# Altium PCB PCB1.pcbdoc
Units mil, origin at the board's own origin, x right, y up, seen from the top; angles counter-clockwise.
Board outline 2533.91 x 1370 mil, 2 copper layers (Top Layer, Bottom Layer); 22 components, 28 nets, 122 pads, 66 vias.
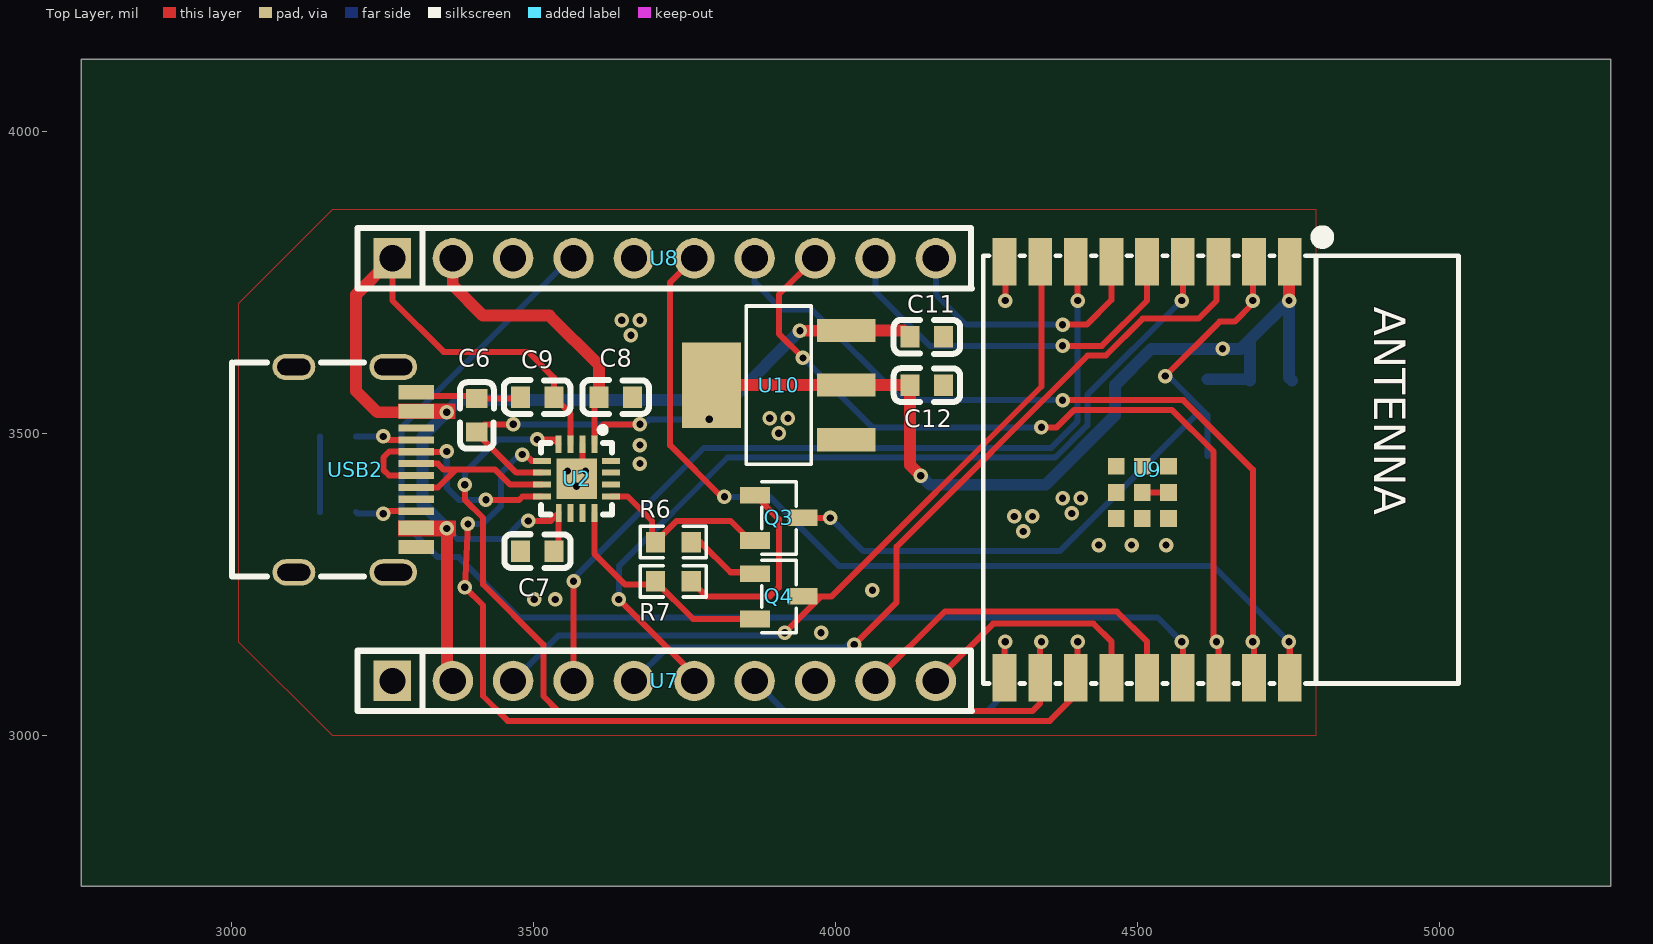
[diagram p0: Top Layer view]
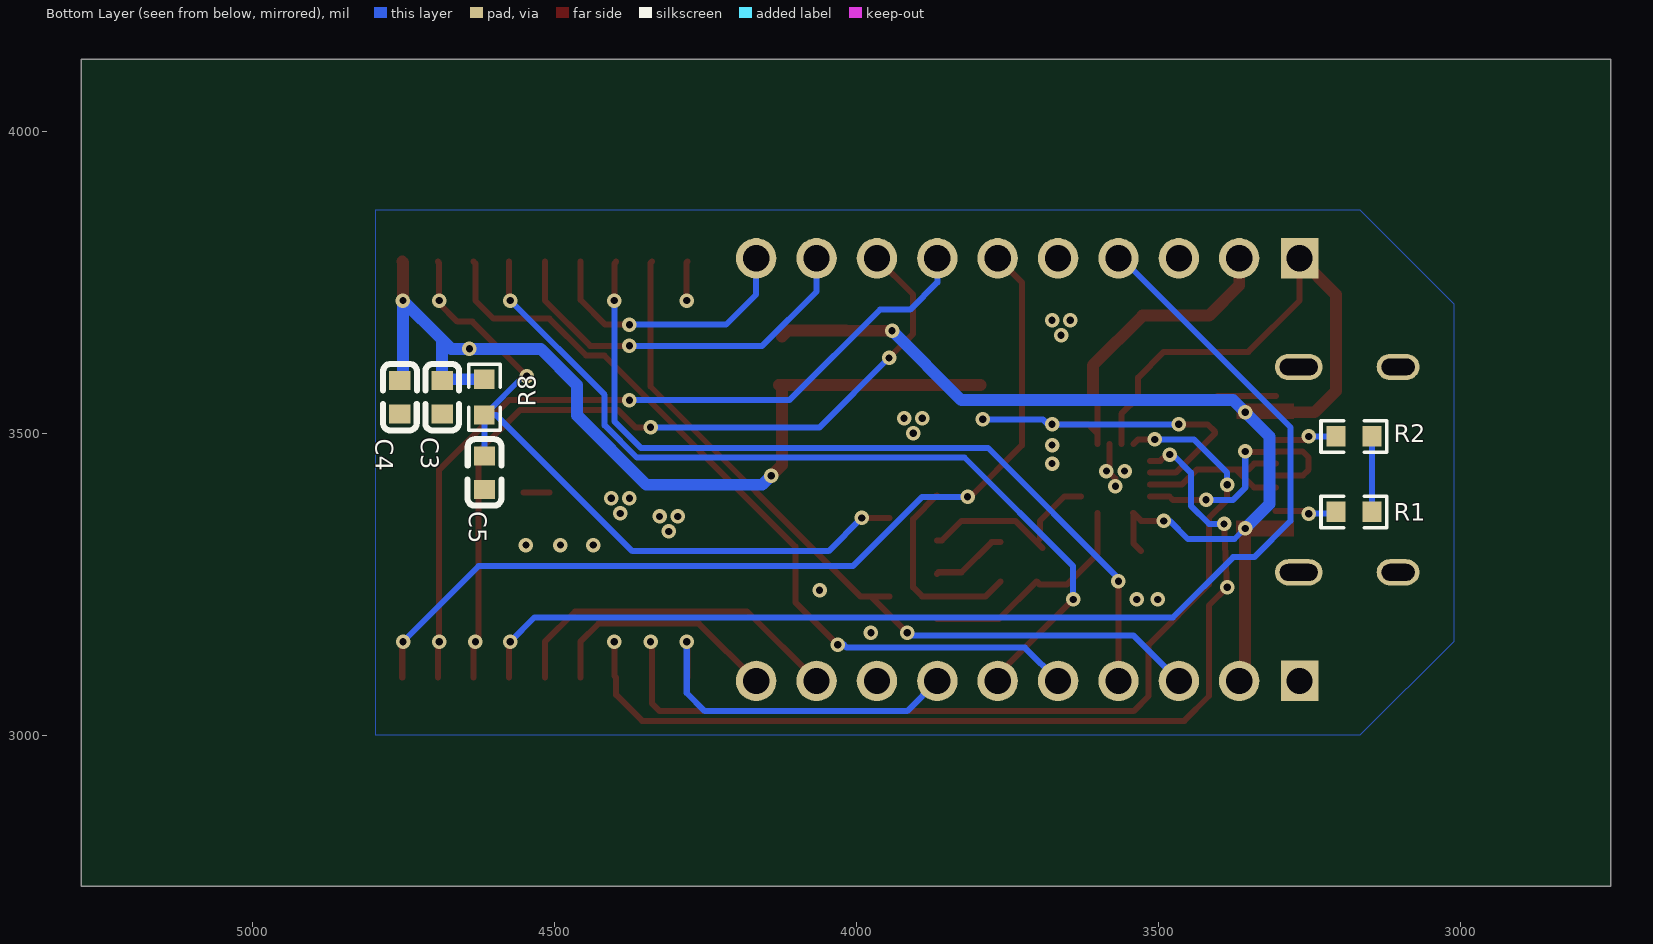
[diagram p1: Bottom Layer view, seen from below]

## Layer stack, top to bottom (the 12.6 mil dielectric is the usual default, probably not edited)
Top Solder: solder mask 0.4, Solder Resist, Dk 3.5
Top Layer: signal copper 1.4
Dielectric 1: dielectric 12.6, FR-4, Dk 4.8
Bottom Layer: signal copper 1.4
Bottom Solder: solder mask 0.4, Solder Resist, Dk 3.5

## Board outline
5283.91,2750 2750,2750 2750,4120 5283.91,4120

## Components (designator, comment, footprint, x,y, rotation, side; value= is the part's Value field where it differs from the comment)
C3 "0603F104Z500CT" C0603 4685.82,3559.7 r270 bottom
C4 "0603F104Z500CT" C0603 4755.82,3559.7 r270 bottom
C5 "0603F104Z500CT" C0603 4615.71,3435 r270 bottom
C6 "CC0603KRX7R8BB105" C0603 3405.71,3530 r90 top
C7 "CC0603KRX7R8BB105" C0603 3505.71,3305 r180 top
C8 "CC0603KRX7R8BB105" C0603 3635.71,3560 r0 top
C9 "0603F104Z500CT" C0603 3505.71,3560 r0 top
C11 "JMK107BC6106MA-T" C0603 4150.71,3660 r180 top
C12 "JMK107BC6106MA-T" C0603 4150.71,3580 r180 top
Q3 "S8050" SOT-23-3_L2.9-W1.3-P1.90-LS2.4-BR 3905.71,3360 r180 top
Q4 "S8050" SOT-23-3_L2.9-W1.3-P1.90-LS2.4-BR 3905.71,3230 r180 top
R1 "0603" R0603 3175.71,3370 r0 bottom
R2 "0603" R0603 3175.71,3495 r180 bottom
R6 "0603" R0603 3731.01,3320 r0 top
R7 "0603" R0603 3731.01,3255 r0 top
R8 "0603" R0603 4615.71,3560 r90 bottom
U2 "CH343P" TQFN-16_L3.0-W3.0-P0.50-BL-EP1.7 3570.71,3425 r180 top
U7 "cn10_2r54_10x1" HDR-TH_10P-P2.54-V-F 3715.71,3090 r0 top
U8 "cn10_2r54_10x1" HDR-TH_10P-P2.54-V-F 3715.71,3790 r0 top
U9 "ESP32-C3-WROOM-02D-N4" BULETM-SMD_18P-L20.0-W18.0-P1.50_ESP32-C3-WROOM 4515.71,3440 r270 top
U10 "AMS1117-1.5" SOT-223-4_L6.5-W3.5-P2.30-LS7.0-BR 3905.71,3580 r0 top
USB2 "TYPE-C母座16P" TYPE-C-SMD_16P-EH4 3203.9,3440 r270 top

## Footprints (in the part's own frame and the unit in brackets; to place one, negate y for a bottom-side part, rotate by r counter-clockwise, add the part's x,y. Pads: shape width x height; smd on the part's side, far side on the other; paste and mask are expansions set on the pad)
BULETM-SMD_18P-L20.0-W18.0-P1.50_ESP32-C3-WROOM [mil]
  rect 78.7x39.4 smd: 1(-344.5,236.2) 2(-344.5,177.2) 3(-344.5,118.1) 4(-344.5,59.1) 5(-344.5,0) 6(-344.5,-59) 7(-344.5,-118.1) 8(-344.5,-177.2) 9(-344.5,-236.2) 10(344.5,-236.2) 11(344.5,-177.2) 12(344.5,-118.1) 13(344.5,-59) 14(344.5,0) 15(344.5,59.1) 16(344.5,118.1) 17(344.5,177.2) 18(344.5,236.2)
  rect 27.6x27.6 smd: 19(-5.5,35.4) 19(-5.5,-7.9) 19(-5.5,-51.2) 19(37.8,35.4) 19(37.8,-7.9) 19(37.8,-51.2) 19(81.1,-7.9) 19(81.1,35.4) 19(81.1,-51.2)
  silkscreen extent -395,-272 354,516
C0603 [mm]
  rect 0.8x0.9 smd: 1(-0.7,0) 2(0.7,0)
  silkscreen extent -1.41,-0.71 1.39,0.72
HDR-TH_10P-P2.54-V-F [mil]
  rect 62x66.9 hole 43.3: 1(-450,0)
  round 66.9 hole 43.3: 2(-350,0) 3(-250,0) 4(-150,0) 5(-50,0) 6(50,0) 7(150,0) 8(250,0) 9(350,0) 10(450,0)
  silkscreen extent -508,-50 510,50
R0603 [mil]
  rect 31.75x34.02 smd: 1(-29.66,0) 2(29.66,0)
  silkscreen extent -55,-26 55,26
SOT-23-3_L2.9-W1.3-P1.90-LS2.4-BR [mm]
  rect 1.25x0.7 smd: 1(1,-0.95) 2(1,0.95) 3(-1,0)
  silkscreen extent -0.73,-1.53 0.73,1.53
SOT-223-4_L6.5-W3.5-P2.30-LS7.0-BR [mm]
  rect 2.47x0.98 smd: 1(2.835,-2.3) 2(2.835,0) 3(2.835,2.3)
  rect 2.47x3.6 smd: 4(-2.835,0)
  silkscreen extent -1.37,-3.33 1.37,3.33
TQFN-16_L3.0-W3.0-P0.50-BL-EP1.7 [mm]
  rect 0.25x0.75 smd: 1(-0.748,-1.45) 2(-0.249,-1.45) 3(0.252,-1.45) 4(0.751,-1.45) 9(0.75,1.45) 10(0.25,1.45) 11(-0.25,1.45) 12(-0.749,1.45)
  rect 0.75x0.25 smd: 5(1.45,-0.75) 6(1.45,-0.25) 7(1.45,0.25) 8(1.45,0.75) 13(-1.45,0.75) 14(-1.45,0.25) 15(-1.45,-0.25) 16(-1.45,-0.75)
  rect 1.7x1.7 smd: 17(0,0)
  silkscreen extent -1.5,-2.17 1.5,1.5
TYPE-C-SMD_16P-EH4 [mil]
  oval 43.3x78.7 hole 27.6 slot 63 at 90 deg: 1(-170.1,63.2) 1(170.1,63.2)
  oval 43.3x70.9 hole 27.6 slot 55.1 at 90 deg: 1(-170.1,-101.3) 1(170.1,-101.3)
  rect 11.8x59.1 smd: A1(-133.9,101.3) A4(-102.4,101.3) A5(-49.2,101.3) A6(-9.8,101.3) A7(9.8,101.3) A8(49.2,101.3) A9(102.4,101.3) A12(133.9,101.3) B1(122.1,101.3) B4(90.6,101.3) B5(68.9,101.3) B6(29.5,101.3) B7(-29.5,101.3) B8(-68.9,101.3) B9(-90.5,101.3) B12(-122,101.3)
  silkscreen extent -177,-204 177,15

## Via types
v1: diameter 24.02, hole 12.01, Top Layer to Bottom Layer, 66 vias

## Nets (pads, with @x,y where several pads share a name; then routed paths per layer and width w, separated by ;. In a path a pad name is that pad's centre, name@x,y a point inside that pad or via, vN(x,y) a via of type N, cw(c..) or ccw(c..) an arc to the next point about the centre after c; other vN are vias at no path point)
3V3: C3.1 C4.1 C6.1 C8.1 C12.2 R8.2 U2.1 U2.6 U8.2 U9.1 U10.2 U10.4 | length 2690.9
  Top Layer w10: v1(3465.71,3515) 3418.27,3515 C6.1 3405.71,3500 3470.87,3434.84 U2.6 ; U2.1 3600.18,3499.47 ; C8.1 3600.18,3552.03 3600.18,3499.47 ; v1(3675.71,3515) 3665.12,3515 3615.71,3515 3600.18,3499.47
  Top Layer w19.68: U8.2 3365.71,3745 3415.71,3695 3525.71,3695 3608.15,3612.56 C8.1 ; U10.4 U10.2 C12.2 ; C12.2@4128.27,3580 C12.2 ; v1(4140.71,3430) 4123.15,3447.56 C12.2 ; v1(4750.68,3719.97) 4750.68,3783.27 U9.1
  Bottom Layer w10: v1(3465.71,3515) 3682.57,3515 3690.84,3523.28 v1(3790.33,3523.28)
  Bottom Layer w19.68: v1(4140.71,3430) 4155.71,3415 4347.81,3415 4462.49,3529.67 4462.49,3580.06 4522.43,3640 v1(4640.71,3640) 4670.71,3640 4685.82,3655.11 ; R8.2 4683.41,3589.66 C3.1 4685.82,3655.11 ; C4.1 4750.68,3592.39 v1(4750.68,3719.97) 4685.82,3655.11
$1N1679: R1.2 USB2.B5 | length 102.7
  Top Layer w10: v1(3250.71,3367.05) 3254.77,3371.1 USB2.B5
  Bottom Layer w10: R1.2 3208.33,3367.05 v1(3250.71,3367.05)
$1N1773: R2.1 USB2.A5 | length 102.2
  Top Layer w10: v1(3250.71,3495) 3256.51,3489.2 USB2.A5
  Bottom Layer w10: R2.1 v1(3250.71,3495)
$1N6356: Q3.1 R7.2 | length 330.3
  Top Layer w10: R7.2 3785.71,3230 3890.71,3230 3905.71,3245 3905.71,3358.03 Q3.1
$1N6357: Q4.1 R6.2 | length 127.4
  Top Layer w10: R6.2 3775.71,3320 3825.71,3270 3863.74,3270 Q4.1
+5V: C7.1 C9.2 C11.2 U2.3 U2.9 U7.2 U8.1 U10.3 USB2.A4 USB2.A9 USB2.B4 USB2.B9 | length 2437.4
  Top Layer w10: U8.1 3265.71,3720 3350.71,3635 3490.71,3635 3533.27,3592.44 C9.2 3560.81,3532.47 U2.3 ; v1(3490.71,3355) 3528.28,3355 U2.9@3540.71,3367.43 ; C7.1@3528.27,3305 3540.71,3317.44 U2.9@3540.71,3367.43 ; U2.9 U2.9@3540.71,3367.43
  Top Layer w19.68: U8.1 3205.71,3730 3205.71,3570 3240.71,3535 USB2.B9@3278.39,3535 ; v1(3355.87,3342.64) 3355.87,3099.84 U7.2 ; v1(3940.71,3670) 4016.77,3670 U10.3 4112.6,3670.55 C11.2
  Bottom Layer w10: v1(3355.87,3342.64) 3373.51,3325 3450.71,3325 3480.71,3355 v1(3490.71,3355) v1@3490.71,3350
  Bottom Layer w19.68: v1(3355.87,3342.64) 3315.71,3382.8 3315.71,3495 v1(3355.71,3535) 3375.71,3555 3825.71,3555 v1(3940.71,3670)
D+: U2.7 USB2.A6 USB2.B6 | length 300.5
  Top Layer w10: USB2.B6 3341.21,3410.5 3370.34,3439.63 3370.34,3440 ; USB2.A6 3340.91,3449.8 3350.71,3440 3370.34,3440 ; U2.7 3513.48,3415 3460.71,3415 3435.71,3440 3370.34,3440
D-: U2.8 USB2.A7 USB2.B7 | length 416.6
  Top Layer w10: USB2.A7 3260.51,3430.2 3250.71,3440 3250.71,3460 3260.71,3470 3304.7,3470 USB2.B7 3355.21,3469.5 v1(3355.71,3470) ; v1(3420.71,3390) 3475.71,3390 3481.18,3395.47 U2.8
  Bottom Layer w10: v1(3355.71,3470) 3355.71,3410 3375.71,3390 v1(3420.71,3390)
DTR: Q4.2 R7.1 U2.12 | length 382.4
  Top Layer w10: U2.12 3600.21,3300.51 3650.71,3250 3696.31,3250 3701.31,3255 3763.71,3192.6 Q4.2
EN: C5.1 Q3.3 R8.1 U9.2 | length 1216.4
  Top Layer w10: Q3.3 v1(3990.71,3360) ; v1(4545.71,3595) 4635.71,3685 4660.71,3685 4690.74,3715.03 4690.74,3782.33 U9.2
  Bottom Layer w10: v1(3990.71,3360) 4045.71,3305 4370.71,3305 4596.05,3530.34 R8.1 ; v1(4545.71,3595) 4551.05,3595 R8.1 ; C5.1 R8.1
  other v1: 4690.74,3720
GND: C3.2 C4.2 C5.2 C6.2 C7.2 C8.2 C9.1 C11.1 C12.1 R1.1 R2.2 U2.2 U2.17 U7.1 U7.8 U8.3 U9.9 U9.19 U10.1 USB2.1 USB2.A1 USB2.A12 USB2.B1 USB2.B12 | length 470.3
  Top Layer w10: USB2.B12 3401.27,3562 C6.2 3475.71,3557.56 C9.1 ; U2.17 3580.5,3434.8 U2.2 ; U9.9 4280.74,3783.27 v1(4280.74,3720) ; U9.19@4507.81,3402.2 U9.19@4551.11,3402.2
  Bottom Layer w10: R1.1 R2.2
  other v1: 3975.71,3170 3500.71,3225 3535.33,3225 4060.71,3240 4435.71,3315 4489.8,3315 4546.95,3315 4310.71,3337.5 4295.71,3362.5 4325.71,3362.5 4390.71,3367.5 4375.71,3392.5 4405.71,3392.5 3570.7,3412.5 3555.7,3437.5 3585.7,3437.5 3675.71,3450 3675.71,3480.7 3905.71,3500.17 3890.71,3525.17 3920.71,3525.17 3660.71,3662.5 3645.71,3687.5 3675.71,3687.5
IO0: U8.6 U9.18 | length 1551.1
  Top Layer w10: U8.6 3725.71,3750 3725.71,3480 3810.71,3395 v1(3815.71,3395) ; v1(4750.65,3155) 4751.91,3153.74 U9.18
  Bottom Layer w10: v1@3810.71,3395 3890.71,3395 4005.71,3280 4625.65,3280 v1(4750.65,3155)
IO1: U8.7 U9.17 | length 1343.8
  Top Layer w10: v1@4375.71,3560 v1(4375.71,3555) 4575.71,3555 4690.71,3440 v1(4690.71,3155) 4692.91,3152.8 U9.17
  Bottom Layer w10: U8.7 3865.71,3750 3910.71,3705 3960.71,3705 4110.71,3555 v1(4375.71,3555)
IO2: U8.8 U9.16 | length 1352.5
  Top Layer w10: v1(3945.71,3625) 3905.71,3665 3905.71,3730 U8.8 ; v1(4340.71,3510) 4365.71,3510 4394.71,3539 4556.71,3539 4625.71,3470 4625.71,3159.96 v1(4630.67,3155) 4633.81,3151.86 U9.16
  Bottom Layer w10: v1(3945.71,3625) 4060.71,3510 v1(4340.71,3510)
IO3: U8.4 U9.15 | length 1991.3
  Top Layer w10: v1(4572.98,3155) 4574.81,3153.17 U9.15
  Bottom Layer w10: U8.4 3560.71,3790 3280.71,3510 3280.71,3355 3340.71,3295 3375.71,3295 3475.71,3195 4532.98,3195 v1(4572.98,3155)
IO4: U7.5 U9.3 | length 1345.9
  Top Layer w10: v1(4030.71,3150) 4100.71,3220 4100.71,3312.54 4417.17,3629 4447.3,3629 4508.3,3690 4600.7,3690 4630.7,3720 4630.7,3781.39 U9.3
  Bottom Layer w10: U7.5 3720.71,3145 4015.71,3145 4020.71,3150 v1(4030.71,3150)
IO5: U7.6 U9.4 | length 1451.1
  Top Layer w10: v1(3640.71,3225) 3765.71,3100 U7.6 ; v1(4573.01,3720) 4574.81,3721.8 U9.4
  Bottom Layer w10: v1(3640.71,3225) 3640.71,3280 3820.71,3460 4363.34,3460 4416.71,3513.37 4416.71,3563.7 v1(4573.01,3720)
IO6: U8.9 U9.5 | length 642.8
  Top Layer w10: v1@4375.71,3650 v1(4375.71,3645) 4440.68,3645 4515.68,3720 ; 4515.71,3720.03 U9.5
  Bottom Layer w10: U8.9 4065.71,3735 4155.71,3645 v1(4375.71,3645)
IO7: U8.10 U9.6 | length 452.2
  Top Layer w10: v1(4375.71,3680) 4415.71,3680 4456.71,3721 U9.6
  Bottom Layer w10: U8.10 4165.71,3730 4215.71,3680 v1(4375.71,3680)
IO8: U7.4 U9.7 | length 1373.5
  Top Layer w10: U7.4 v1(3565.71,3255) ; U9.7 4400.71,3781.4 v1(4400.71,3720)
  Bottom Layer w10: v1@3565.71,3260 3781.71,3476 4356.71,3476 4400.71,3520 v1(4400.71,3720)
IO9: Q4.3 U7.3 U9.8 | length 1308.4
  Top Layer w10: v1(3915.71,3170) 3975.71,3230 ; Q4.3 3975.71,3230 ; U9.8 4340.74,3782.27 4340.74,3577.66 3993.08,3230 3975.71,3230
  Bottom Layer w10: U7.3 3540.71,3165 v1@3910.71,3165
IO10: U7.7 U9.10 | length 593.1
  Top Layer w10: U9.10 4279.51,3153.8 v1(4280.71,3155)
  Bottom Layer w10: U7.7 3915.71,3040 4250.71,3040 4280.71,3070 v1(4280.71,3155)
IO18: U7.10 U9.13 | length 402.5
  Top Layer w10: U7.10 4260.71,3185 4426.89,3185 4456.89,3155 4456.71,3154.82 U9.13
IO19: U7.9 U9.14 | length 577.7
  Top Layer w10: U7.9 4180.71,3205 4465.64,3205 4515.64,3155 ; U9.14 4515.71,3154.93
RTS: Q3.2 R6.1 U2.13 | length 328.4
  Top Layer w10: U2.13 3655.24,3395.47 3695.71,3355 3695.71,3325.6 R6.1@3701.31,3320 ; R6.1@3691.78,3310.47 R6.1@3701.31,3320 ; Q3.2 3858.11,3322.6 3825.71,3355 3736.31,3355 R6.1@3701.31,3320
RXD0: U2.4 U9.11 | length 1546.9
  Top Layer w10: v1(3385.71,3415) 3385.71,3390 3415.71,3360 3415.71,3250 3515.71,3150 3515.71,3065 3540.71,3040 4325.71,3040 4338.51,3052.8 U9.11 4338.51,3152.8 v1(4340.71,3155) ; v1(3505.71,3490) 3533.22,3490 U2.4
  Bottom Layer w10: v1(3385.71,3415) 3385.71,3435 3440.71,3490 v1(3505.71,3490)
TXD0: U2.5 U9.12 | length 1610.7
  Top Layer w10: v1(3390.71,3350) v1(3385.71,3245) 3415.71,3215 3415.71,3065 3456.71,3024 4354.71,3024 4397.61,3066.9 U9.12 4400.71,3098.6 v1(4400.71,3155) ; v1(3480.71,3465) 3485.71,3465 3496.19,3454.52 U2.5
  Bottom Layer w10: v1(3390.71,3350) 3415.71,3350 3445.71,3380 3445.71,3435 3475.71,3465 v1(3480.71,3465)
"": 
pads on no net: U2.10 U2.11 U2.14 U2.15 U2.16 U8.5 USB2.A8 USB2.B8

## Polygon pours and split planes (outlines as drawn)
GND on Top Layer (solid, remove dead copper): 3165.71,3870 3010.71,3715 3010.71,3155 3165.71,3000 4795.71,3000 4795.71,3870
GND on Bottom Layer (solid, remove dead copper, pour order 1): 3165.71,3870 3010.71,3715 3010.71,3155 3165.71,3000 4795.71,3000 4795.71,3870

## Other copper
Top Layer:
  region net +5V: 3275.71,3330 3370.71,3330 3370.71,3355 3275.71,3355
  region net +5V: 3275.14,3523.96 3370.14,3523.96 3370.14,3548.96 3275.14,3548.96

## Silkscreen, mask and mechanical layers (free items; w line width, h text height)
Mechanical 1:
  lines w10: 3010.71,3155 3010.71,3715 3165.71,3870 3195.71,3870 4795.71,3870 4795.71,3000 3195.71,3000 3165.71,3000 3010.71,3155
